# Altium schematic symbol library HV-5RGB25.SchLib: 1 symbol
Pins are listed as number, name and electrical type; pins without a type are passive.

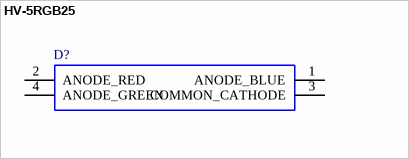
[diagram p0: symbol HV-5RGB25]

## HV-5RGB25
designator D?
Standard LEDs - Through Hole RGB LED; Manufacturer_Name: Inolux; Geometry.Height: 8.9mm
footprint HV5RGB25
pins: 1 ANODE_BLUE, 2 ANODE_RED, 3 COMMON_CATHODE, 4 ANODE_GREEN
